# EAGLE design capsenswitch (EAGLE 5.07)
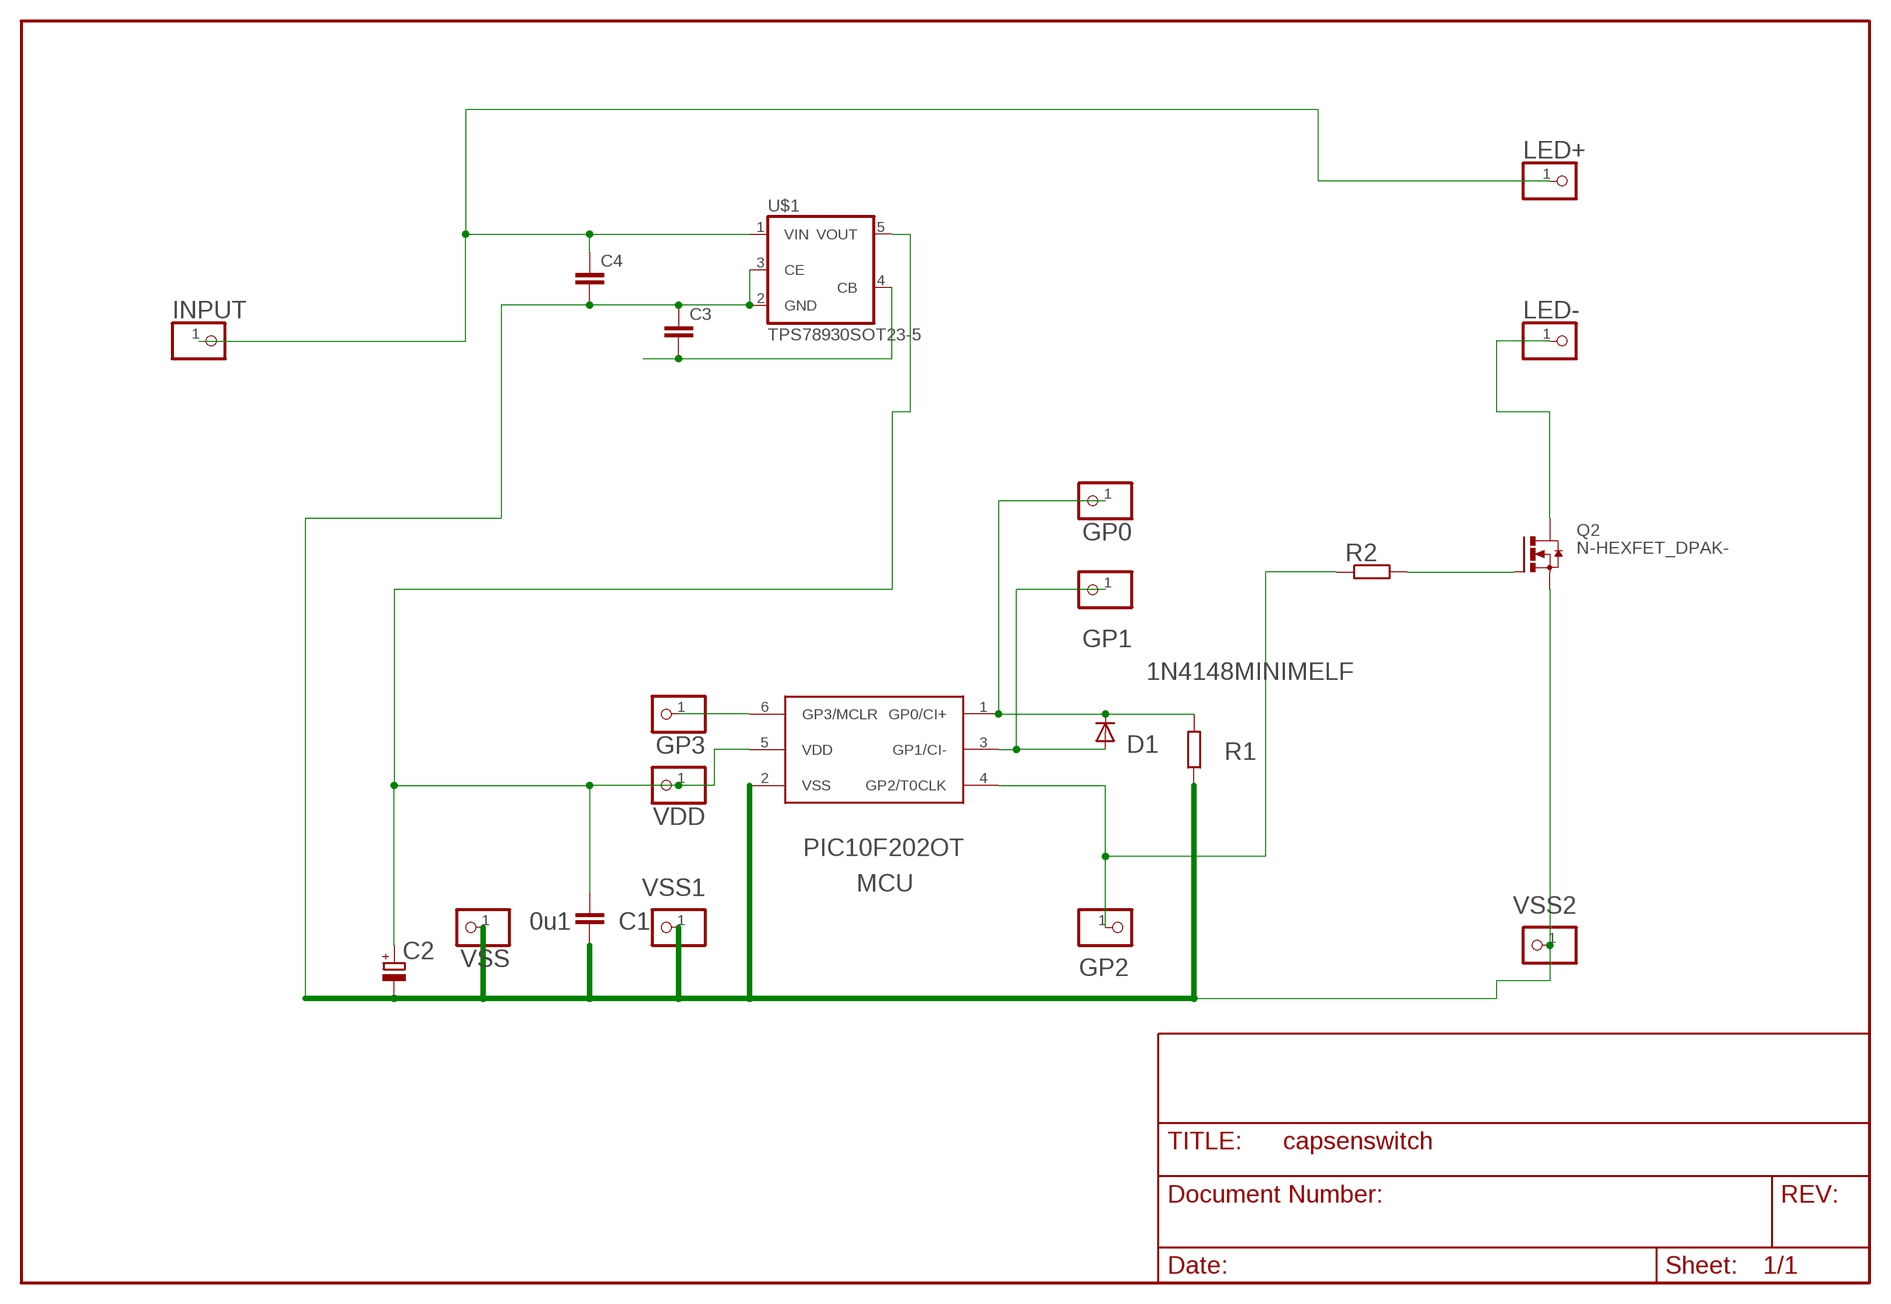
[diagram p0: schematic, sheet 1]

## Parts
C1  0u1  C-EUC1206  [C1206]
C2  CPOL-EUSMCB  [SMC_B]
C3  C-EUC0805  [C0805]
C4  C-EUC1206  [C1206]
D1  1N4148MINIMELF  [MINIMELF]
GP0  PINHD-1X1  [1X01]
GP1  PINHD-1X1  [1X01]
GP2  PINHD-1X1  [1X01]
GP3  PINHD-1X1  [1X01]
INPUT  PINHD-1X1  [1X01]
LED+  PINHD-1X1  [1X01]
LED-  PINHD-1X1  [1X01]
MCU  PIC10F202OT  [SOT23-6]
Q2  N-HEXFET_DPAK-  [TO252]
R1  R-EU_R0805  [R0805]
R2  R-EU_R0805  [R0805]
U$1  TPS78930SOT23-5  [SOT25]
VDD  PINHD-1X1  [1X01]
VSS  PINHD-1X1  [1X01]
VSS1  PINHD-1X1  [1X01]
VSS2  PINHD-1X1  [1X01]

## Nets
GND: C1.1 C2.- C3.1 C4.2 MCU.2(VSS) Q2.2(S) R1.1 U$1.2(GND) U$1.3(CE) VSS1.1 VSS2.1 VSS.1
GP0: D1.C GP0.1 MCU.1(GP0/CI+) R1.2
GP1: D1.A GP1.1 MCU.3(GP1/CI-)
GP2: GP2.1 MCU.4(GP2/T0CLK) R2.1
GP3: GP3.1 MCU.6(GP3/MCLR)
HOT: LED-.1 Q2.3(D)
N$3: Q2.1(G) R2.2
N$11: C3.2 U$1.4(CB)
V5: C4.1 INPUT.1 LED+.1 U$1.1(VIN)
VDD1: C1.2 C2.+ MCU.5(VDD) U$1.5(VOUT) VDD.1

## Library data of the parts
C1 C3 C4 = rcl:C-EU: CAPACITOR, European symbol
C2 = rcl-2:CPOL-EU: POLARIZED CAPACITOR, European symbol
D1 = diode-1:1N4148: DIODE
GP0 GP1-GP3 INPUT LED+ LED- VDD VSS VSS1 VSS2 = pinhead(2):PINHD-1X1: PIN HEADER
MCU = microchip-3:PIC10F2*: uPC nW 0,25/0,5k Program Flash memory Comparator
Q2 = transistor-power:N-HEXFET_?-*: HEXFET® Power MOSFET
R1 R2 = rcl-2:R-EU_: RESISTOR, European symbol
U$1 = v-reg:TPS78930

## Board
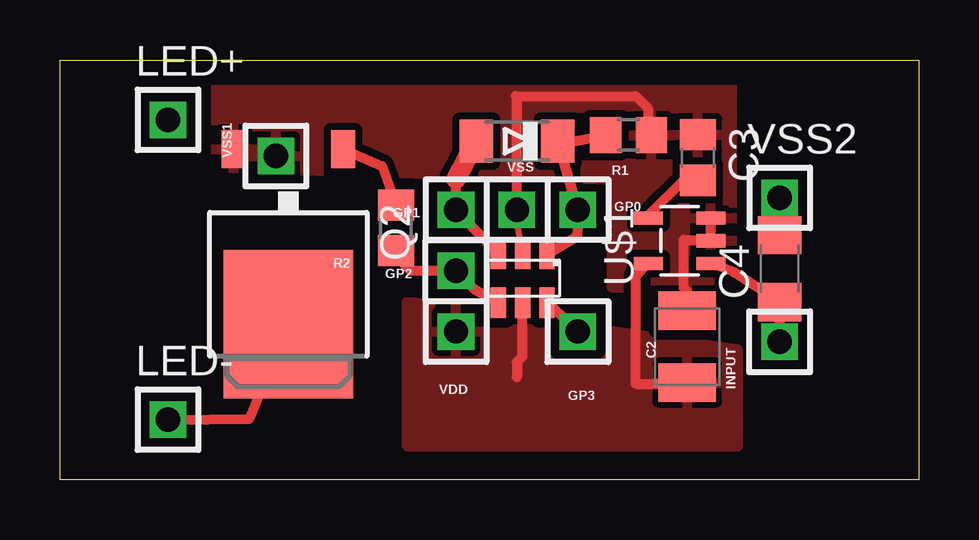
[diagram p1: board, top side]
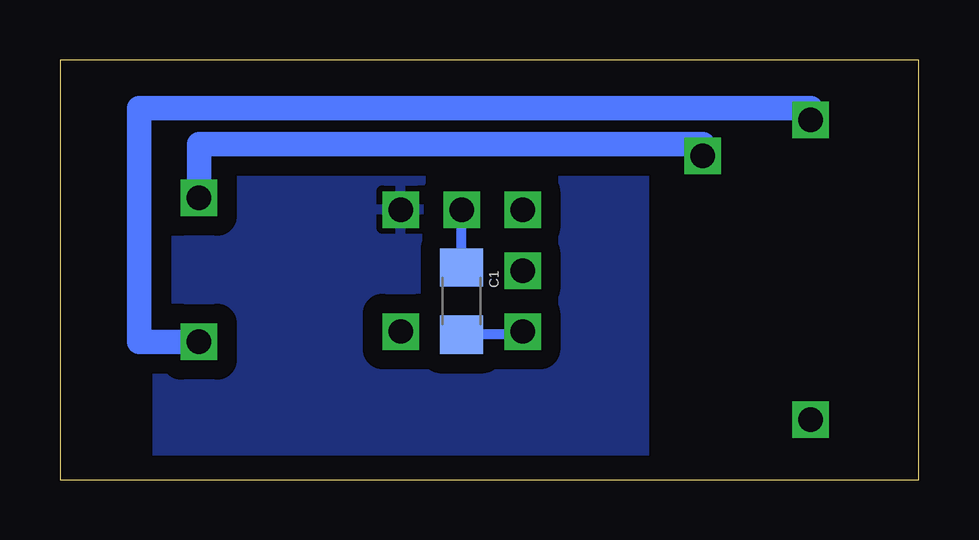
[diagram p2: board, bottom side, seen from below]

Size 35.8 x 17.5 mm. Coordinates in mm from the lower left corner, seen from the top.
Outline: 0,0 0,17.5 35.8,17.5 35.8,0 0,0
Copper layers (1*16): Top 0.035mm / dielectric 1.5mm / Bottom 0.035mm
Design rules "default": minimum track width 10mil, minimum drill 24mil, track to track 8mil, track to pad 8mil, pad to pad 8mil, via to via 8mil, smd to smd 8mil, copper to edge 40mil, drill to drill 8mil, minimum pad ring 10mil, minimum via ring 8mil, stop-mask expansion 4mil, vias tented up to drill 0mil, thermal gap 10mil

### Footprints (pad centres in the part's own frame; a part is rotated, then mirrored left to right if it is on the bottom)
C1206 = smd 1.6 x 1.8: 1 -1.4,0; 2 1.4,0
SMC_B = smd 1.6 x 2.4: + -1.5,0; - 1.5,0
C0805 = smd 1.3 x 1.5: 1 -0.95,0; 2 0.95,0
MINIMELF = smd 1.4 x 1.8: A 1.7,0; C -1.7,0
1X01 = drill 1.016 square: 1 0,0
SOT23-6 = smd 0.635 x 1.27: 1 -1.016,-1.016; 2 0,-1.016; 3 1.016,-1.016; 4 1.016,1.016; 5 0,1.016; 6 -1.016,1.016
TO252 = smd 1 x 1.6: 1 -2.28,-3.53; 2 2.28,-3.53 | smd 5.4 x 6.2: 3 0,3.77
R0805 = smd 1.3 x 1.5: 1 -0.95,0; 2 0.95,0
SOT25 = smd 0.55 x 1.2: 1 -0.95,-1.3; 2 0,-1.3; 3 0.95,-1.3; 4 0.95,1.3; 5 -0.95,1.3

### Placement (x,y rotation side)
C1  19.05,7.45 270 bottom
C2  26.15,5.54 90 top
C3  26.59,13.43 270 top
C4  30,8.8 90 top
D1  19.05,14.11 180 top
GP0  21.59,11.26 0 top
GP1  16.51,11.26 0 top
GP2  16.51,8.71 90 top
GP3  21.59,6.17 0 top
INPUT  30,5.75 90 top
LED+  4.5,15 0 top
LED-  4.5,2.5 0 top
MCU  19.29,8.4 180 top
Q2  9.53,10.25 180 top
R1  23.7,14.37 180 top
R2  14,10.5 90 top
U$1  25.83,9.96 90 top
VDD  16.51,6.17 0 top
VSS  19.05,11.26 0 top
VSS1  9,13.5 90 top
VSS2  30,11.75 0 top

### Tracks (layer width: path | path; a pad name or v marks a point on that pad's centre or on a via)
GND
  Top 0.254: MCU.2 19.05,10.62 VSS.1
  Top 0.406: U$1.3 U$1.2 27.09,10 26,10 26,8 26.15,7.85 C2.- | VSS2.1 C4.2 | VSS.1 19.05,15.95 19,16 24,16 24.5,15.5 24.5,14.52 R1.1
  Bottom 0.406: C1.1 VSS.1
  Bottom 1.016: VSS2.1 30,14 9,14 VSS1.1
  pour Top (isolate 0.305, rank 2): 6.5,13 6.5,16.5 28,16.5 28,8 23,8 23,12.5
GP0
  Top 0.406: MCU.1 21.57,10.15 21.59,10.48 GP0.1 D1.C 21.46,14.11 R1.2
  pour Bottom (isolate 0.813): 11.43,17.14 31.75,17.14 31.75,-0.64 11.43,-0.64
GP1
  Top 0.406: MCU.3 GP1.1 16.51,12.53
  Top 0.813: 16.51,12.53 D1.A
GP2
  Top 0.406: MCU.4 17.29,7.93 GP2.1 14.61,8.71 13.97,9.35 R2.1
GP3
  Top 0.406: MCU.6 GP3.1
HOT
  Top 0.406: LED-.1 7.9,2.54 Q2.3
N$3
  Top 0.406: R2.2 13.42,13.08 Q2.1
N$11
  Top 0.406: U$1.4 24.53,11.03 26,12.5 26.58,12.5 C3.2
V5
  Top 0.406: U$1.1 28.09,8.65 C4.1 INPUT.1
  Bottom 1.016: INPUT.1 32.5,5.75 32.5,15.5 4.5,15.5 LED+.1
VDD1
  Top 0.406: MCU.5 19.27,5.13 19.05,4.91 19.05,4.27 | U$1.5 24.51,9.01 24,8.5 24,4 26.11,4 C2.+
  Bottom 0.406: C1.2 17.14,6.04 VDD.1
  pour Top (isolate 0.406): 14.47,7.45 28.25,5.45 28.25,1.36 14.47,1.36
